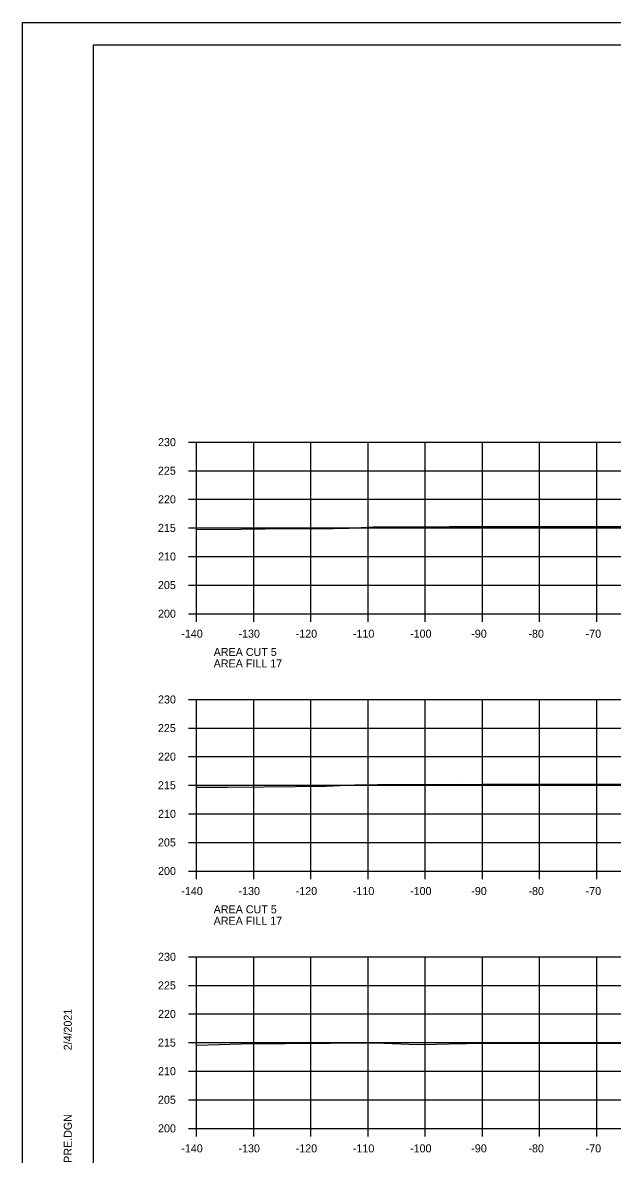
# Model space of a CAD drawing. Extents: x 1368968 to 1369915, y 377395 to 380381.
# Drawn here: x 1369581.4 to 1369684.5, y 378050.1 to 378248 of the extents above; entities that cross this region are included whole.
import ezdxf

# ---------------------------------------------------------------- set-up
doc = ezdxf.new("R2010")
doc.units = 0
for name, color, linetype in [('S_BREAKLINE_ANNOT', 7, 'Continuous'), ('S_BRIDGE', 7, 'Continuous'), ('S_BRIDGE_ANNOT', 7, 'Continuous'), ('S_CTL_TABLE', 7, 'Continuous'), ('S_DITCHLINE_ANNOT', 7, 'Continuous'), ('S_DROP_INLET', 7, 'Continuous')]:
    doc.layers.add(name, color=color, linetype=linetype)

msp = doc.modelspace()

# ---------------------------------------------------------------- linework, layer by layer
at = {"layer": 'S_BREAKLINE_ANNOT'}
for p, q in [((1369610.38, 378174.69), (1369611.78, 378174.69)), ((1369611.78, 378144.69), (1369611.78, 378174.69)), ((1369610.38, 378169.69), (1369611.78, 378169.69)), ((1369610.38, 378164.69), (1369611.78, 378164.69)), ((1369610.38, 378159.69), (1369611.78, 378159.69)), ((1369610.38, 378154.69), (1369611.78, 378154.69)), ((1369610.38, 378149.69), (1369611.78, 378149.69)), ((1369610.38, 378144.69), (1369611.78, 378144.69)), ((1369611.78, 378144.69), (1369891.78, 378144.69)), ((1369611.78, 378143.29), (1369611.78, 378144.69)), ((1369621.78, 378143.29), (1369621.78, 378144.69)), ((1369631.78, 378143.29), (1369631.78, 378144.69)), ((1369641.78, 378143.29), (1369641.78, 378144.69)), ((1369651.78, 378143.29), (1369651.78, 378144.69)), ((1369661.78, 378143.29), (1369661.78, 378144.69)), ((1369671.78, 378143.29), (1369671.78, 378144.69)), ((1369681.78, 378143.29), (1369681.78, 378144.69)), ((1369610.38, 378129.69), (1369611.78, 378129.69)), ((1369611.78, 378099.69), (1369611.78, 378129.69)), ((1369610.38, 378124.69), (1369611.78, 378124.69)), ((1369610.38, 378119.69), (1369611.78, 378119.69)), ((1369610.38, 378114.69), (1369611.78, 378114.69)), ((1369610.38, 378109.69), (1369611.78, 378109.69)), ((1369610.38, 378104.69), (1369611.78, 378104.69)), ((1369610.38, 378099.69), (1369611.78, 378099.69)), ((1369611.78, 378099.69), (1369891.78, 378099.69)), ((1369611.78, 378098.29), (1369611.78, 378099.69)), ((1369621.78, 378098.29), (1369621.78, 378099.69)), ((1369631.78, 378098.29), (1369631.78, 378099.69)), ((1369641.78, 378098.29), (1369641.78, 378099.69)), ((1369651.78, 378098.29), (1369651.78, 378099.69)), ((1369661.78, 378098.29), (1369661.78, 378099.69)), ((1369671.78, 378098.29), (1369671.78, 378099.69)), ((1369681.78, 378098.29), (1369681.78, 378099.69)), ((1369610.38, 378084.69), (1369611.78, 378084.69)), ((1369611.78, 378054.69), (1369611.78, 378084.69)), ((1369610.38, 378079.69), (1369611.78, 378079.69)), ((1369610.38, 378074.69), (1369611.78, 378074.69)), ((1369610.38, 378069.69), (1369611.78, 378069.69)), ((1369610.38, 378064.69), (1369611.78, 378064.69)), ((1369610.38, 378059.69), (1369611.78, 378059.69)), ((1369610.38, 378054.69), (1369611.78, 378054.69)), ((1369611.78, 378054.69), (1369891.78, 378054.69)), ((1369611.78, 378053.29), (1369611.78, 378054.69)), ((1369621.78, 378053.29), (1369621.78, 378054.69)), ((1369631.78, 378053.29), (1369631.78, 378054.69)), ((1369641.78, 378053.29), (1369641.78, 378054.69)), ((1369651.78, 378053.29), (1369651.78, 378054.69)), ((1369661.78, 378053.29), (1369661.78, 378054.69)), ((1369671.78, 378053.29), (1369671.78, 378054.69)), ((1369681.78, 378053.29), (1369681.78, 378054.69))]:
    msp.add_line(p, q, dxfattribs=at)
at = {"layer": 'S_BRIDGE_ANNOT'}
for p, q in [((1369593.78, 378244.15), (1369909.96, 378244.15)), ((1369593.78, 378038.69), (1369593.78, 378244.15))]:
    msp.add_line(p, q, dxfattribs=at)
at = {"layer": 'S_CTL_TABLE'}
for points in [[(1369611.78, 378159.4), (1369619.61, 378159.46), (1369623.8, 378159.5), (1369635.74, 378159.59), (1369638.47, 378159.65), (1369642.64, 378159.89), (1369655.97, 378159.94), (1369661.65, 378159.95), (1369670.96, 378159.94), (1369677.2, 378159.96), (1369678.17, 378159.96), (1369687.02, 378159.95)], [(1369611.78, 378114.35), (1369617.18, 378114.38), (1369623.53, 378114.43), (1369634.46, 378114.5), (1369639.41, 378114.77), (1369643.45, 378114.8), (1369658.22, 378114.85), (1369659.61, 378114.84), (1369661.78, 378114.88), (1369662.27, 378114.89), (1369664.16, 378114.88), (1369674.87, 378114.88), (1369677.16, 378114.87), (1369689.26, 378114.87)], [(1369611.78, 378069.21), (1369619.6, 378069.45), (1369627.29, 378069.53), (1369643.07, 378069.64), (1369648.96, 378069.44), (1369651.47, 378069.33), (1369655.9, 378069.45), (1369662.09, 378069.6), (1369662.72, 378069.61), (1369666.37, 378069.59), (1369695.39, 378069.61)]]:
    msp.add_lwpolyline(points, dxfattribs=at)
at = {"layer": 'S_DITCHLINE_ANNOT'}
for p, q in [((1369611.78, 378174.69), (1369891.78, 378174.69)), ((1369611.78, 378144.69), (1369611.78, 378174.69)), ((1369621.78, 378144.69), (1369621.78, 378174.69)), ((1369631.78, 378144.69), (1369631.78, 378174.69)), ((1369641.78, 378144.69), (1369641.78, 378174.69)), ((1369651.78, 378144.69), (1369651.78, 378174.69)), ((1369661.78, 378144.69), (1369661.78, 378174.69)), ((1369671.78, 378144.69), (1369671.78, 378174.69)), ((1369681.78, 378144.69), (1369681.78, 378174.69)), ((1369611.78, 378169.69), (1369891.78, 378169.69)), ((1369611.78, 378164.69), (1369891.78, 378164.69)), ((1369611.78, 378159.69), (1369891.78, 378159.69)), ((1369611.78, 378154.69), (1369891.78, 378154.69)), ((1369611.78, 378149.69), (1369891.78, 378149.69)), ((1369611.78, 378144.69), (1369891.78, 378144.69)), ((1369611.78, 378129.69), (1369891.78, 378129.69)), ((1369611.78, 378099.69), (1369611.78, 378129.69)), ((1369621.78, 378099.69), (1369621.78, 378129.69)), ((1369631.78, 378099.69), (1369631.78, 378129.69)), ((1369641.78, 378099.69), (1369641.78, 378129.69)), ((1369651.78, 378099.69), (1369651.78, 378129.69)), ((1369661.78, 378099.69), (1369661.78, 378129.69)), ((1369671.78, 378099.69), (1369671.78, 378129.69)), ((1369681.78, 378099.69), (1369681.78, 378129.69)), ((1369611.78, 378124.69), (1369891.78, 378124.69)), ((1369611.78, 378119.69), (1369891.78, 378119.69)), ((1369611.78, 378114.69), (1369891.78, 378114.69)), ((1369611.78, 378109.69), (1369891.78, 378109.69)), ((1369611.78, 378104.69), (1369891.78, 378104.69)), ((1369611.78, 378099.69), (1369891.78, 378099.69)), ((1369611.78, 378084.69), (1369891.78, 378084.69)), ((1369611.78, 378054.69), (1369611.78, 378084.69)), ((1369621.78, 378054.69), (1369621.78, 378084.69)), ((1369631.78, 378054.69), (1369631.78, 378084.69)), ((1369641.78, 378054.69), (1369641.78, 378084.69)), ((1369651.78, 378054.69), (1369651.78, 378084.69)), ((1369661.78, 378054.69), (1369661.78, 378084.69)), ((1369671.78, 378054.69), (1369671.78, 378084.69)), ((1369681.78, 378054.69), (1369681.78, 378084.69)), ((1369611.78, 378079.69), (1369891.78, 378079.69)), ((1369611.78, 378074.69), (1369891.78, 378074.69)), ((1369611.78, 378069.69), (1369891.78, 378069.69)), ((1369611.78, 378064.69), (1369891.78, 378064.69)), ((1369611.78, 378059.69), (1369891.78, 378059.69)), ((1369611.78, 378054.69), (1369891.78, 378054.69))]:
    msp.add_line(p, q, dxfattribs=at)
at = {"layer": 'S_DROP_INLET'}
msp.add_line((1369581.38, 378248.05), (1369914.71, 378248.05), dxfattribs=at)
for points in [[(1369581.37, 378248.05), (1369914.71, 378248.05), (1369914.71, 378034.71), (1369581.37, 378034.71)], [(1369827.7, 378244.15), (1369827.7, 378234.27), (1369863.43, 378234.27), (1369863.43, 378231.35), (1369886.63, 378231.35), (1369886.63, 378207.02), (1369909.96, 378207.02), (1369909.96, 378038.69), (1369593.78, 378038.69), (1369593.78, 378244.15)]]:
    msp.add_lwpolyline(points, close=True, dxfattribs=at)

# ---------------------------------------------------------------- texts
at = {"layer": 'S_BRIDGE'}
for s, p in [('230', (1369605.05, 378173.99)), ('225', (1369605.03, 378168.99)), ('220', (1369605.05, 378163.99)), ('215', (1369605.03, 378158.99)), ('210', (1369605.05, 378153.99)), ('205', (1369605.03, 378148.99)), ('200', (1369605.05, 378143.99)), ('-140', (1369609.12, 378140.49)), ('-130', (1369619.12, 378140.49)), ('-120', (1369629.12, 378140.49)), ('-110', (1369639.12, 378140.49)), ('-100', (1369649.12, 378140.49)), ('-90', (1369659.82, 378140.49)), ('-80', (1369669.82, 378140.49)), ('-70', (1369679.82, 378140.49)), ('AREA CUT 5', (1369614.78, 378137.29)), ('AREA FILL 17', (1369614.78, 378135.29)), ('230', (1369605.05, 378128.99)), ('225', (1369605.03, 378123.99)), ('220', (1369605.05, 378118.99)), ('215', (1369605.03, 378113.99)), ('210', (1369605.05, 378108.99)), ('205', (1369605.03, 378103.99)), ('200', (1369605.05, 378098.99)), ('-140', (1369609.12, 378095.49)), ('-130', (1369619.12, 378095.49)), ('-120', (1369629.12, 378095.49)), ('-110', (1369639.12, 378095.49)), ('-100', (1369649.12, 378095.49)), ('-90', (1369659.82, 378095.49)), ('-80', (1369669.82, 378095.49)), ('-70', (1369679.82, 378095.49)), ('AREA CUT 5', (1369614.78, 378092.29)), ('AREA FILL 17', (1369614.78, 378090.29)), ('230', (1369605.05, 378083.99)), ('225', (1369605.03, 378078.99)), ('220', (1369605.05, 378073.99)), ('215', (1369605.03, 378068.99)), ('210', (1369605.05, 378063.99)), ('205', (1369605.03, 378058.99)), ('200', (1369605.05, 378053.99)), ('-140', (1369609.12, 378050.49)), ('-130', (1369619.12, 378050.49)), ('-120', (1369629.12, 378050.49)), ('-110', (1369639.12, 378050.49)), ('-100', (1369649.12, 378050.49)), ('-90', (1369659.82, 378050.49)), ('-80', (1369669.82, 378050.49)), ('-70', (1369679.82, 378050.49))]:
    msp.add_text(s, height=1.4, dxfattribs=at).set_placement(p)
at = {"layer": 'S_BRIDGE_ANNOT'}
for s, p in [('2/4/2021', (1369589.97, 378068.33)), ('R020588_PRE.DGN', (1369589.97, 378040.02))]:
    msp.add_text(s, height=1.4, rotation=90, dxfattribs=at).set_placement(p)

doc.saveas('drawing.dxf')
